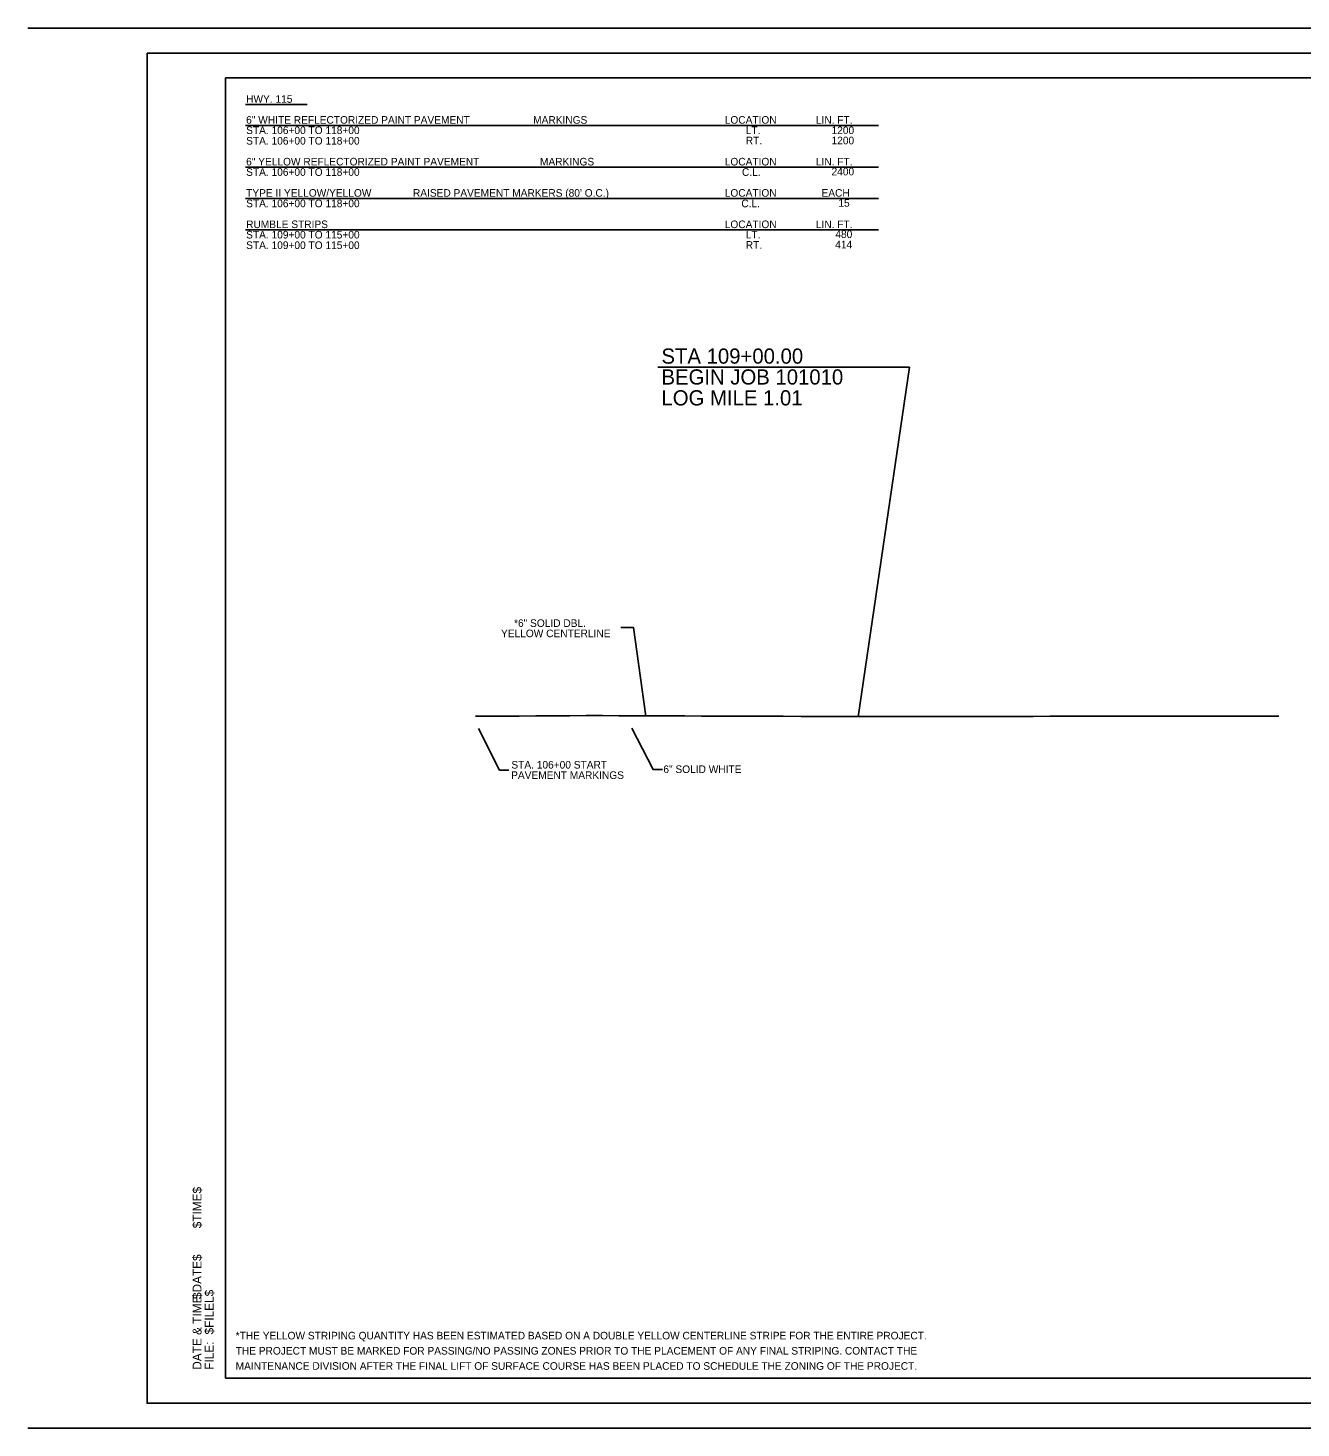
# Model space of a CAD drawing. Extents: x 9844 to 11605, y 9961 to 11067.
# Drawn here: x 9844 to 10850, y 9961 to 11067 of the extents above; entities that cross this region are included whole.
import ezdxf

# ---------------------------------------------------------------- set-up
doc = ezdxf.new("R2010")
doc.units = 0
for name, color, linetype in [('GREEN_TXT', 7, 'Continuous'), ('S_PAVEMENT_CROWN', 7, 'Continuous'), ('SEAL-INFO', 7, 'Continuous'), ('STA Text', 7, 'Continuous'), ('TEXT', 7, 'Continuous')]:
    doc.layers.add(name, color=color, linetype=linetype)

msp = doc.modelspace()

# ---------------------------------------------------------------- linework, layer by layer
at = {"layer": 'GREEN_TXT'}
for p, q in [((11603.9, 11066.7), (9843.9, 11066.7)), ((10000, 11027.3), (11580.9, 11027.3)), ((10000, 10000), (10000, 11027.3)), ((10762.6, 11026), (10762.6, 11026)), ((10762.6, 11026), (10762.6, 11026)), ((11580.9, 10000), (10000, 10000)), ((9843.9, 9960.6), (11603.9, 9960.6))]:
    msp.add_line(p, q, dxfattribs=at)
at = {"layer": 'S_PAVEMENT_CROWN'}
msp.add_lwpolyline([(10197.5, 10523), (10205.2, 10523.1), (10218.6, 10523.1), (10232, 10523.1), (10245.3, 10523.2), (10258.5, 10523.3), (10271.8, 10523.3), (10285, 10523.4), (10297.9, 10523.4), (10310.9, 10523.3), (10323.8, 10523.3), (10336.7, 10523.3), (10349.8, 10523.2), (10362.9, 10523.2), (10376.1, 10523.1), (10389.2, 10523), (10402.1, 10523), (10414.9, 10523), (10427.8, 10522.9), (10440.6, 10522.9), (10454.8, 10522.8), (10468.9, 10522.8), (10483.1, 10522.8), (10497.3, 10522.7), (10521.6, 10522.7), (10545.8, 10522.7), (10559, 10522.7), (10572.2, 10522.7), (10585.4, 10522.7), (10598.5, 10522.7), (10611.8, 10522.7), (10625, 10522.8), (10638.2, 10522.8), (10651.4, 10522.9), (10664.8, 10522.9), (10678.2, 10523), (10691.6, 10523.1), (10705, 10523.1), (10718, 10523.1), (10730.9, 10523.1), (10743.9, 10523.1), (10756.8, 10523.1), (10770, 10523), (10783.3, 10523), (10796.5, 10522.9), (10809.7, 10522.9), (10832.3, 10522.9)], dxfattribs=at)
at = {"layer": 'SEAL-INFO'}
for points in [[(9938, 11046.8), (11604.7, 11046.8), (11604.7, 9980.1), (9938, 9980.1)], [(10000, 10000), (11580.9, 10000), (11580.3, 10963.3), (11365.4, 10963.3), (11357.3, 10959.9), (11348.5, 10961.4), (11348.3, 10977.9), (11169.6, 10977.9), (11169.6, 11027.3), (10000, 11027.3)], [(10000, 10000), (11580.9, 10000), (11580.3, 10963.3), (11365.4, 10963.3), (11357.3, 10959.9), (11348.5, 10961.4), (11348.3, 10977.9), (11169.6, 10977.9), (11169.6, 11027.3), (10000, 11027.3)], [(10000, 10000), (11580.9, 10000), (11580.3, 10963.3), (11365.4, 10963.3), (11357.3, 10959.9), (11348.5, 10961.4), (11348.3, 10977.9), (11169.6, 10977.9), (11169.6, 11027.3), (10000, 11027.3)]]:
    msp.add_lwpolyline(points, close=True, dxfattribs=at)
at = {"layer": 'STA Text'}
msp.add_lwpolyline([(10341.5, 10798.7), (10540.4, 10798.7), (10500, 10522.5)], dxfattribs=at)
at = {"layer": 'TEXT'}
for p, q in [((10015.9, 11006.2), (10064.4, 11006.2)), ((10015.9, 10989.7), (10515.9, 10989.7)), ((10015.9, 10956.7), (10515.9, 10956.7)), ((10015.9, 10931.9), (10515.9, 10931.9)), ((10015.9, 10907.2), (10515.9, 10907.2))]:
    msp.add_line(p, q, dxfattribs=at)
for points in [[(10312.5, 10593), (10322.5, 10593), (10332.1, 10522.9)], [(10224, 10480.4), (10216.6, 10480.4), (10200, 10513.2)], [(10345.2, 10480.8), (10337.8, 10480.8), (10321.2, 10513.6)]]:
    msp.add_lwpolyline(points, dxfattribs=at)

# ---------------------------------------------------------------- texts
for s, height, p in [('$TIME$', 6.98, (9981, 10118.4)), ('$DATE$', 6.98, (9981, 10062.5)), ('DATE & TIME:', 6.984, (9981, 10006.6)), ('$FILEL$', 6.98, (9990.6, 10034.5)), ('FILE: ', 6.98, (9990.6, 10006.6))]:
    msp.add_text(s, height=height, rotation=90).set_placement(p)
at = {"layer": 'STA Text'}
for s, p in [('STA 109+00.00', (10344.5, 10801.5)), ('BEGIN JOB 101010', (10344.5, 10785)), ('LOG MILE 1.01', (10344.5, 10768.5))]:
    msp.add_text(s, height=12, dxfattribs=at).set_placement(p)
at = {"layer": 'TEXT'}
for s, p in [('HWY. 115', (10016.3, 11007.6)), ('6" WHITE REFLECTORIZED PAINT PAVEMENT ', (10016.3, 10991.1)), ('MARKINGS', (10243.1, 10991.1)), ('LOCATION', (10394.5, 10991.1)), ('LOCATION', (10394.5, 10991.1)), ('LIN. FT.', (10466.5, 10991.1)), ('STA. 106+00 TO 118+00', (10016.3, 10982.9)), ('LT.', (10411.1, 10982.9)), ('1200', (10478.9, 10982.9)), ('STA. 106+00 TO 118+00', (10016.3, 10974.6)), ('RT.', (10411.1, 10974.8)), ('1200', (10478.9, 10974.8)), ('6" YELLOW REFLECTORIZED PAINT PAVEMENT ', (10016.3, 10958.1)), ('MARKINGS', (10248.5, 10958.1)), ('LOCATION', (10394.5, 10958.1)), ('LIN. FT.', (10466.5, 10958.1)), ('STA. 106+00 TO 118+00', (10016.3, 10949.9)), ('C.L.', (10408.1, 10949.9)), ('2400', (10478.9, 10950.3)), ('TYPE II YELLOW/YELLOW ', (10016.3, 10933.4)), ("RAISED PAVEMENT MARKERS (80' O.C.)", (10148.1, 10933.4)), ('LOCATION', (10394.5, 10933.4)), ('  EACH', (10466.5, 10933.4)), ('STA. 106+00 TO 118+00', (10016.3, 10925.1)), ('C.L.', (10407.6, 10925.1)), ('15', (10484.3, 10925.5)), ('STA. 109+00 TO 115+00', (10016.3, 10900.4)), ('RUMBLE STRIPS', (10016.3, 10908.6)), ('LOCATION', (10394.5, 10908.6)), ('LT.', (10411.1, 10900.4)), ('LIN. FT.', (10466.5, 10908.6)), ('480', (10481.9, 10900.8)), ('STA. 109+00 TO 115+00', (10016.3, 10892.1)), ('RT.', (10411.1, 10892.3)), ('414', (10481.8, 10892.6)), ('*6" SOLID DBL.', (10228, 10593.5)), ('YELLOW CENTERLINE', (10217.7, 10585.4)), ('STA. 106+00 START', (10225.9, 10481.6)), ('PAVEMENT MARKINGS', (10225.7, 10473.4)), ('6" SOLID WHITE', (10346, 10478.1)), ('*THE YELLOW STRIPING QUANTITY HAS BEEN ESTIMATED BASED ON A DOUBLE YELLOW CENTERLINE STRIPE FOR THE ENTIRE PROJECT.', (10008, 10030.6)), ('THE PROJECT MUST BE MARKED FOR PASSING/NO PASSING ZONES PRIOR TO THE PLACEMENT OF ANY FINAL STRIPING. CONTACT THE', (10008, 10018.6)), ('MAINTENANCE DIVISION AFTER THE FINAL LIFT OF SURFACE COURSE HAS BEEN PLACED TO SCHEDULE THE ZONING OF THE PROJECT.', (10008, 10006.6))]:
    msp.add_text(s, height=6, dxfattribs=at).set_placement(p)

doc.saveas('drawing.dxf')
